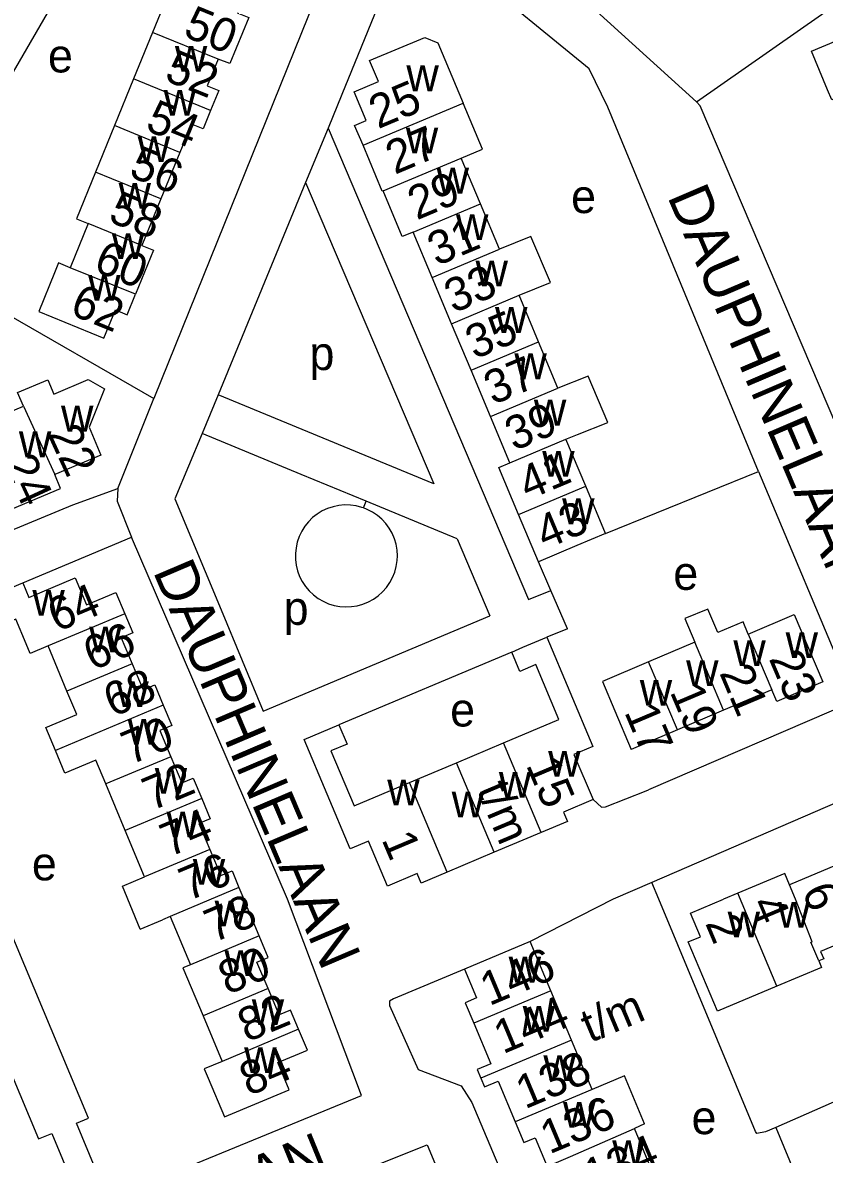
# Model space of a CAD drawing. Extents: x 157768 to 159790, y 387230 to 389604.
# Drawn here: x 158768.4 to 158864.1, y 388469.5 to 388604.7 of the extents above; entities that cross this region are included whole.
import ezdxf

# ---------------------------------------------------------------- set-up
doc = ezdxf.new("R2010")
doc.units = 0
for name, color, linetype in [('BLT_Basislijn', 7, 'Continuous'), ('BLT_Bebouwing', 7, 'Continuous'), ('BLT_Centroide', 7, 'Continuous'), ('BLT_Huisnummer', 7, 'Continuous'), ('BLT_Huisnummer_ tussenligend', 7, 'Continuous'), ('BLT_Huisnummer_reeks', 7, 'Continuous'), ('BLT_Onderverdeling_panden', 7, 'Continuous'), ('BLT_Straatnaam', 7, 'Continuous'), ('BLT_Vlakafsluiter', 7, 'Continuous')]:
    doc.layers.add(name, color=color, linetype=linetype)

msp = doc.modelspace()

# ---------------------------------------------------------------- linework, layer by layer
at = {"layer": 'BLT_Basislijn'}
for p, q in [((158848.78, 388595.18), (158874.98, 388613.54)), ((158804.81, 388592.04), (158802.14, 388585.55)), ((158804.81, 388592.04), (158828.75, 388535.77)), ((158802.14, 388585.55), (158791.68, 388560.24)), ((158802.14, 388585.55), (158817.43, 388549.6)), ((158752.5, 388577.95), (158784, 388559.78)), ((158779.72, 388549.02), (158784, 388559.78)), ((158791.68, 388560.24), (158789.77, 388555.62)), ((158817.43, 388549.6), (158791.68, 388560.24)), ((158801.62, 388550.72), (158789.77, 388555.62)), ((158809.37, 388547.52), (158801.62, 388550.72)), ((158837.95, 388543.66), (158856.2, 388551.05)), ((158820.22, 388543.04), (158809.37, 388547.52)), ((158768.37, 388537.78), (158781.37, 388543.21)), ((158820.22, 388543.04), (158824.14, 388533.83)), ((158831.39, 388536.88), (158829.92, 388540.29)), ((158828.75, 388535.77), (158831.39, 388536.88)), ((158833.38, 388532.3), (158831.39, 388536.88)), ((158792.05, 388534.54), (158797.07, 388522.45)), ((158797.07, 388522.45), (158824.14, 388533.83)), ((158833.38, 388532.3), (158830.93, 388531.28)), ((158826.75, 388529.52), (158806.1, 388520.84)), ((158875.29, 388515.8), (158843.47, 388502.02)), ((158858.27, 388472.75), (158871.67, 388440.58))]:
    msp.add_line(p, q, dxfattribs=at)
for points in [[(158752.5, 388577.95), (158756, 388582.29), (158766.39, 388597.28), (158772.92, 388608.56), (158776.78, 388616.43), (158781.2, 388626.96), (158792.74, 388668.52)], [(158848.78, 388595.18), (158820.24, 388621.14), (158817.54, 388623.31)], [(158809.51, 388621.86), (158808.32, 388620.05), (158784, 388559.78)], [(158856.2, 388551.05), (158838.2, 388594.58), (158835.97, 388599.15), (158821.48, 388611.04), (158818.68, 388612.35), (158817.09, 388612.4), (158813.77, 388611.42), (158811.86, 388609.35), (158806.47, 388596.08), (158804.81, 388592.04)], [(158877.6, 388529.55), (158876.7, 388530.29), (158849.23, 388594.74), (158848.78, 388595.18)], [(158789.77, 388555.62), (158786.54, 388547.79), (158792.05, 388534.54)], [(158856.2, 388551.05), (158867.29, 388524.65), (158867.48, 388523.59), (158843.07, 388513.05)], [(158743.37, 388533.93), (158743.54, 388534.06), (158743.9, 388534.46), (158774.34, 388547.09), (158779.72, 388549.02)], [(158779.72, 388549.02), (158779.65, 388547.53), (158781.37, 388543.21)], [(158809.05, 388546.72), (158808.85, 388546.79), (158808.18, 388546.97), (158807.49, 388547.06), (158806.79, 388547.08), (158806.09, 388547.02), (158805.41, 388546.87), (158804.75, 388546.65), (158804.12, 388546.36), (158803.52, 388545.99), (158802.97, 388545.56), (158802.48, 388545.07), (158802.04, 388544.53), (158801.67, 388543.94), (158801.37, 388543.31), (158801.14, 388542.65), (158800.99, 388541.97), (158800.92, 388541.28), (158800.92, 388540.58), (158801.01, 388539.89), (158801.18, 388539.21), (158801.42, 388538.55), (158801.74, 388537.93), (158802.12, 388537.35), (158802.57, 388536.82), (158803.08, 388536.34), (158803.63, 388535.92), (158804.24, 388535.57), (158804.88, 388535.29), (158805.54, 388535.08), (158806.23, 388534.96), (158806.92, 388534.91), (158807.62, 388534.94), (158808.31, 388535.05), (158808.98, 388535.24), (158809.63, 388535.5), (158810.24, 388535.84), (158810.81, 388536.24), (158811.32, 388536.71), (158811.79, 388537.24), (158812.18, 388537.81), (158812.52, 388538.42), (158812.77, 388539.07), (158812.96, 388539.74), (158813.06, 388540.43), (158813.09, 388540.99)], [(158813.09, 388540.99), (158813.05, 388541.69), (158812.93, 388542.38), (158812.73, 388543.05), (158812.46, 388543.69), (158812.11, 388544.3), (158811.7, 388544.86), (158811.23, 388545.37), (158810.7, 388545.83), (158810.12, 388546.22), (158809.5, 388546.54), (158809.05, 388546.72)], [(158778.58, 388464.15), (158808.82, 388476.57), (158799.98, 388500), (158781.37, 388543.21)], [(158778.58, 388464.15), (158774.78, 388473.27), (158776.21, 388473.86), (158755.39, 388523.57), (158753.12, 388522.63), (158749.99, 388530.03)], [(158748.73, 388529.24), (158751.69, 388522.02), (158749.43, 388521.09), (158770.23, 388471.39), (158771.83, 388472.05), (158775.66, 388462.85)], [(158836.45, 388511.9), (158837.47, 388511.01), (158837.94, 388511.04), (158842.81, 388512.94), (158843.07, 388513.05)], [(158843.47, 388502.02), (158838.86, 388500), (158828.95, 388494.95)], [(158858.27, 388472.75), (158857.02, 388472.22), (158855.99, 388472.03), (158855.83, 388472.28), (158844.29, 388500), (158843.47, 388502.02)], [(158925.92, 388502.32), (158920.27, 388500), (158858.27, 388472.75)], [(158821.11, 388491.65), (158812.62, 388488.1), (158812.14, 388487.84), (158812.15, 388487.34), (158815.59, 388479.7), (158820.7, 388477.74), (158821.99, 388475.76), (158841.52, 388429.43), (158841.92, 388428.6), (158843.29, 388428.39)], [(158743.87, 388438.13), (158745.5, 388438.98), (158746.04, 388441.22), (158804.21, 388465.72), (158816.65, 388470.68), (158826.54, 388446.97)]]:
    msp.add_lwpolyline(points, dxfattribs=at)
at = {"layer": 'BLT_Bebouwing'}
for p, q in [((158783.87, 388603.49), (158781.6, 388597.93)), ((158781.6, 388597.93), (158779.33, 388592.36)), ((158779.33, 388592.36), (158777.05, 388586.8)), ((158787.12, 388589.17), (158784.85, 388583.61)), ((158784.85, 388583.61), (158782.58, 388578.05)), ((158825.28, 388577.63), (158823.02, 388583.01)), ((158776.18, 388580.66), (158774.03, 388575.4)), ((158817.23, 388574.24), (158814.96, 388579.66)), ((158819.56, 388568.71), (158817.23, 388574.24)), ((158829.93, 388566.56), (158827.61, 388572.1)), ((158821.88, 388563.18), (158819.56, 388568.71)), ((158832.26, 388561.03), (158829.93, 388566.56)), ((158824.21, 388557.65), (158821.88, 388563.18)), ((158762.91, 388556.53), (158768.44, 388558.86)), ((158826.53, 388552.12), (158824.21, 388557.65)), ((158835.58, 388549.3), (158833.22, 388554.93)), ((158837.95, 388543.66), (158835.58, 388549.3)), ((158829.92, 388540.29), (158827.55, 388545.92)), ((158828.08, 388530.08), (158830.93, 388531.28)), ((158773.65, 388524.86), (158771.41, 388530.24)), ((158826.75, 388529.52), (158828.08, 388530.08)), ((158848.6, 388530.68), (158843.08, 388528.34)), ((158843.08, 388528.34), (158837.56, 388526)), ((158857.8, 388525.01), (158852.04, 388522.57)), ((158852.04, 388522.57), (158846.52, 388520.23)), ((158801.95, 388519.08), (158806.1, 388520.84)), ((158846.52, 388520.23), (158840.99, 388517.89)), ((158820.13, 388516.3), (158825.75, 388518.67)), ((158814.52, 388513.93), (158820.13, 388516.3)), ((158780.6, 388508.22), (158778.28, 388513.77)), ((158782.91, 388502.69), (158780.6, 388508.22)), ((158865.49, 388504.07), (158859.91, 388501.73)), ((158794.18, 388501.4), (158794.75, 388500)), ((158853.75, 388500.72), (158852.03, 388500)), ((158796.59, 388495.63), (158794.75, 388500)), ((158782.4, 388496.45), (158785.06, 388497.56)), ((158785.96, 388497.95), (158785.06, 388497.56)), ((158785.96, 388497.95), (158788.39, 388492.18)), ((158828.95, 388494.95), (158821.11, 388491.65)), ((158831.42, 388489.07), (158828.95, 388494.95)), ((158833.89, 388483.18), (158831.42, 388489.07)), ((158789.89, 388486.08), (158792.17, 388480.65)), ((158836.36, 388477.3), (158833.89, 388483.18)), ((158842.61, 388473.18), (158841.39, 388472.64))]:
    msp.add_line(p, q, dxfattribs=at)
for points in [[(158786.14, 388609.05), (158783.87, 388603.49)], [(158793.97, 388605.84), (158795.34, 388605.28), (158793.09, 388599.77), (158791.69, 388600.28)], [(158866.33, 388596.02), (158864.95, 388595.44), (158864.45, 388596.63), (158862.51, 388601.23), (158870.62, 388604.65), (158872.04, 388601.29), (158873.41, 388601.87), (158874.43, 388599.44)], [(158808.99, 388590.01), (158807.99, 388592.38), (158809.36, 388592.96), (158807.92, 388596.38), (158810.85, 388597.61), (158809.78, 388600.13), (158816.36, 388602.89), (158817.94, 388602.23), (158820.96, 388595.05)], [(158791.69, 388600.28), (158790.4, 388597.12), (158791.77, 388596.56), (158790.8, 388594.16)], [(158820.72, 388588.47), (158823.27, 388589.54), (158820.96, 388595.05)], [(158790.8, 388594.16), (158789.9, 388591.98), (158788.5, 388592.55), (158787.12, 388589.17)], [(158811.38, 388584.59), (158811.28, 388584.55), (158808.99, 388590.01)], [(158823.02, 388583.01), (158820.72, 388588.47)], [(158777.05, 388586.8), (158774.78, 388581.23), (158776.18, 388580.66)], [(158814.96, 388579.66), (158813.68, 388579.13), (158811.38, 388584.59)], [(158827.61, 388572.1), (158831.38, 388573.63), (158829.03, 388579.13), (158825.28, 388577.63)], [(158782.58, 388578.05), (158783.98, 388577.48), (158781.84, 388572.22)], [(158774.03, 388575.4), (158772.65, 388575.97), (158772.16, 388574.78), (158770.27, 388570.15), (158778.06, 388566.97), (158779.44, 388570.35), (158780.84, 388569.78), (158781.84, 388572.22)], [(158833.22, 388554.93), (158834.58, 388555.5), (158838.2, 388556.92), (158835.88, 388562.45), (158832.26, 388561.03)], [(158768.44, 388558.86), (158767.76, 388560.48), (158771.37, 388562), (158772.07, 388560.32), (158776.19, 388562.05), (158778.13, 388560.94), (158776.28, 388556.38), (158777.7, 388553.02), (158772.19, 388550.7)], [(158827.55, 388545.92), (158825.19, 388551.55), (158826.53, 388552.12)], [(158766.39, 388548.28), (158767.1, 388546.61), (158772.89, 388549.05), (158772.19, 388550.7)], [(158837.95, 388543.66), (158834.53, 388542.23), (158829.92, 388540.29)], [(158768.37, 388537.78), (158769.09, 388536.04), (158774.63, 388538.36)], [(158774.63, 388538.36), (158775.97, 388535.17), (158779.49, 388536.64), (158780.57, 388534.07)], [(158758.68, 388533.72), (158768.37, 388537.78)], [(158780.57, 388534.07), (158781.52, 388531.8), (158780.13, 388531.22), (158781.43, 388528.11)], [(158854.98, 388531.66), (158854.36, 388533.12), (158851.34, 388531.84), (158850.17, 388534.65), (158847.42, 388533.52), (158848.6, 388530.68)], [(158854.98, 388531.66), (158860.47, 388533.99), (158863.89, 388525.94), (158858.39, 388523.61), (158857.8, 388525.01)], [(158771.41, 388530.24), (158769.27, 388529.34), (158768.78, 388530.5), (158767.55, 388533.45), (158760.1, 388530.33), (158758.68, 388533.72)], [(158830.93, 388531.28), (158836.44, 388518.25), (158834.17, 388517.29), (158836.45, 388511.9)], [(158825.75, 388518.67), (158832.38, 388521.48), (158829.62, 388528.01), (158827.72, 388527.21), (158826.75, 388529.52)], [(158781.43, 388528.11), (158782.73, 388525.01), (158784.13, 388525.59), (158785.14, 388523.16)], [(158837.56, 388526), (158839.04, 388522.49), (158840.99, 388517.89)], [(158772.27, 388517.78), (158771.13, 388520.5), (158774.83, 388522.05), (158773.65, 388524.86)], [(158785.14, 388523.16), (158786.16, 388520.74), (158784.73, 388520.14), (158786.03, 388517.01)], [(158806.1, 388520.84), (158807.08, 388518.52), (158805.16, 388517.71), (158807.93, 388511.14), (158814.52, 388513.93)], [(158778.28, 388513.77), (158777.1, 388516.6), (158773.41, 388515.06), (158772.27, 388517.78)], [(158819.03, 388503.24), (158815.94, 388501.93), (158815.45, 388503.07), (158811.93, 388501.58), (158809.65, 388506.95), (158807.47, 388506.02), (158801.95, 388519.08)], [(158786.03, 388517.01), (158787.34, 388513.89), (158788.72, 388514.47), (158789.73, 388512.05)], [(158789.73, 388512.05), (158790.75, 388509.62), (158789.4, 388509.06), (158790.71, 388505.95)], [(158836.45, 388511.9), (158832.92, 388510.41), (158833.39, 388509.3), (158830.27, 388507.98)], [(158830.27, 388507.98), (158824.65, 388505.61)], [(158790.71, 388505.95), (158792.01, 388502.84), (158793.38, 388503.41), (158794.18, 388501.4)], [(158824.65, 388505.61), (158819.03, 388503.24)], [(158859.91, 388501.73), (158859.34, 388503.07), (158853.75, 388500.72)], [(158782.4, 388496.45), (158780.26, 388501.58), (158782.91, 388502.69)], [(158858.4, 388489.62), (158851.3, 388486.64), (158847.82, 388494.92), (158849.26, 388495.52), (158848.08, 388498.34), (158852.03, 388500)], [(158797.65, 388489.34), (158796.32, 388492.5), (158797.66, 388493.07), (158796.59, 388495.63)], [(158868.6, 388495.86), (158863.62, 388493.77), (158863.99, 388492.89), (158863.39, 388492.64)], [(158788.39, 388492.18), (158787.48, 388491.8), (158789.89, 388486.08)], [(158863.39, 388492.64), (158863.72, 388491.86), (158858.4, 388489.62)], [(158821.11, 388491.65), (158822.55, 388488.23), (158821.18, 388487.65), (158822.21, 388485.2)], [(158801.3, 388484.49), (158800.34, 388486.76), (158798.98, 388486.19), (158797.65, 388489.34)], [(158792.17, 388480.65), (158790.04, 388479.76), (158790.51, 388478.63), (158792.45, 388474.02), (158800.18, 388477.27), (158798.82, 388480.5), (158802.35, 388481.98), (158801.3, 388484.49)], [(158822.21, 388485.2), (158824.24, 388480.35), (158822.63, 388479.68), (158823.06, 388478.64)], [(158823.06, 388478.64), (158823.5, 388477.6), (158825.11, 388478.28), (158827.15, 388473.43)], [(158842.61, 388473.18), (158840.21, 388478.91), (158836.36, 388477.3)], [(158827.15, 388473.43), (158828.18, 388470.97), (158829.55, 388471.54), (158830.99, 388468.12), (158833.75, 388469.28)], [(158843.74, 388467.05), (158843.24, 388468.23), (158841.39, 388472.64)]]:
    msp.add_lwpolyline(points, dxfattribs=at)
at = {"layer": 'BLT_Onderverdeling_panden'}
for p, q in [((158791.69, 388600.28), (158783.87, 388603.49)), ((158790.8, 388594.16), (158781.6, 388597.93)), ((158808.99, 388590.01), (158820.96, 388595.05)), ((158787.12, 388589.17), (158779.33, 388592.36)), ((158784.85, 388583.61), (158777.05, 388586.8)), ((158814.96, 388579.66), (158823.02, 388583.01)), ((158782.58, 388578.05), (158776.18, 388580.66)), ((158817.23, 388574.24), (158825.28, 388577.63)), ((158781.84, 388572.22), (158774.03, 388575.4)), ((158819.56, 388568.71), (158827.61, 388572.1)), ((158821.88, 388563.18), (158829.93, 388566.56)), ((158824.21, 388557.65), (158832.26, 388561.03)), ((158768.44, 388558.86), (158772.19, 388550.7)), ((158826.53, 388552.12), (158833.22, 388554.93)), ((158827.55, 388545.92), (158835.58, 388549.3)), ((158780.57, 388534.07), (158771.41, 388530.24)), ((158854.98, 388531.66), (158857.8, 388525.01)), ((158852.04, 388522.57), (158848.6, 388530.68)), ((158781.43, 388528.11), (158773.65, 388524.86)), ((158846.52, 388520.23), (158843.08, 388528.34)), ((158785.14, 388523.16), (158772.27, 388517.78)), ((158830.27, 388507.98), (158825.75, 388518.67)), ((158786.03, 388517.01), (158778.28, 388513.77)), ((158824.65, 388505.61), (158820.13, 388516.3)), ((158819.03, 388503.24), (158814.52, 388513.93)), ((158789.73, 388512.05), (158780.6, 388508.22)), ((158790.71, 388505.95), (158782.91, 388502.69)), ((158794.18, 388501.4), (158785.96, 388497.95)), ((158858.4, 388489.62), (158853.75, 388500.72)), ((158796.59, 388495.63), (158788.39, 388492.18)), ((158797.65, 388489.34), (158789.89, 388486.08)), ((158831.42, 388489.07), (158822.21, 388485.2)), ((158801.3, 388484.49), (158792.17, 388480.65)), ((158833.89, 388483.18), (158823.06, 388478.64)), ((158836.36, 388477.3), (158827.15, 388473.43))]:
    msp.add_line(p, q, dxfattribs=at)
for points in [[(158811.38, 388584.59), (158820.72, 388588.47)], [(158863.39, 388492.64), (158862.45, 388494.87), (158862.6, 388494.93), (158860.63, 388500), (158859.91, 388501.73)], [(158833.75, 388469.28), (158841.39, 388472.64)]]:
    msp.add_lwpolyline(points, dxfattribs=at)
at = {"layer": 'BLT_Vlakafsluiter'}
msp.add_line((158809.05, 388546.72), (158809.37, 388547.52), dxfattribs=at)

# ---------------------------------------------------------------- texts
at = {"layer": 'BLT_Centroide'}
for s, p in [('e', (158771.38, 388598.71)), ('w', (158786.53, 388598.81)), ('w', (158814.17, 388596.47)), ('w', (158785.18, 388593.56)), ('w', (158814.1, 388589.06)), ('w', (158782.09, 388588)), ('w', (158817.77, 388584.25)), ('w', (158779.81, 388582.44)), ('e', (158833.83, 388581.92)), ('w', (158820.09, 388578.69)), ('w', (158779.01, 388576.44)), ('w', (158822.42, 388573.16)), ('w', (158776.17, 388571.47)), ('w', (158824.75, 388567.62)), ('p', (158802.6, 388563.18)), ('w', (158827.06, 388562.09)), ('w', (158772.94, 388555.84)), ('w', (158829.39, 388556.56)), ('w', (158767.91, 388552.78)), ('w', (158830.38, 388550.44)), ('w', (158832.76, 388544.78)), ('e', (158846.03, 388536.94)), ('w', (158769.52, 388533.84)), ('p', (158799.51, 388532.76)), ('w', (158776.3, 388529.47)), ('w', (158859.44, 388528.81)), ('w', (158853.2, 388527.84)), ('w', (158847.56, 388525.45)), ('w', (158779.54, 388522.94)), ('w', (158842.03, 388523.12)), ('e', (158819.39, 388520.63)), ('w', (158780.88, 388518.47)), ('w', (158831.09, 388514.64)), ('w', (158784.13, 388512.62)), ('w', (158825.2, 388512.14)), ('w', (158811.88, 388511.22)), ('w', (158819.58, 388509.77)), ('w', (158785.53, 388507.38)), ('e', (158769.46, 388502.26)), ('w', (158788.67, 388501.75)), ('w', (158791.27, 388496.78)), ('w', (158858.48, 388496.62)), ('w', (158852.52, 388495.45)), ('w', (158792.45, 388490.84)), ('w', (158826.38, 388490.06)), ('w', (158795.71, 388485)), ('w', (158828.05, 388484.19)), ('w', (158794.8, 388479.25)), ('w', (158830.52, 388478.31)), ('w', (158832.87, 388472.72)), ('e', (158848.21, 388471.96)), ('w', (158838.74, 388468.16))]:
    msp.add_text(s, height=4, dxfattribs=at).set_placement(p)
at = {"layer": 'BLT_Huisnummer'}
for s, rotation, p in [('50', 337.7261, (158787.37, 388603.1)), ('25', 22.803, (158810.78, 388591.92)), ('54', 337.7261, (158782.85, 388591.88)), ('29', 22.803, (158815.41, 388581.04)), ('58', 337.7261, (158778.42, 388580.99)), ('33', 22.8021, (158819.78, 388569.93)), ('62', 337.7261, (158773.84, 388569.89)), ('37', 22.7986, (158824.51, 388558.98)), ('22', 294.6958, (158771.28, 388555.57)), ('43', 22.7909, (158830.7, 388541.73)), ('64', 22.7113, (158772.43, 388531.86)), ('23', 292.9748, (158857.4, 388528.74)), ('68', 22.7113, (158779.11, 388521.7)), ('17', 292.9654, (158840.14, 388522.37)), ('72', 22.7113, (158783.74, 388510.52)), ('76', 22.7113, (158788.12, 388499.75)), ('6', 292.8103, (158861.34, 388500.99)), ('2', 292.8103, (158849.8, 388497.16)), ('80', 22.7113, (158792.8, 388488.56)), ('146', 22.7679, (158824.06, 388487.23)), ('84', 22.7113, (158795.33, 388476.47)), ('136', 22.7679, (158831.24, 388469.53)), ('134', 22.7679, (158836.38, 388464.92))]:
    msp.add_text(s, height=4, rotation=rotation, dxfattribs=at).set_placement(p)
at = {"layer": 'BLT_Huisnummer_ tussenligend'}
for s, rotation, p in [('52', 337.8006, (158785.13, 388597.83)), ('27', 22.803, (158812.78, 388586.48)), ('56', 337.8006, (158780.89, 388586.36)), ('31', 22.8021, (158817.78, 388575.55)), ('60', 337.8006, (158776.66, 388575.08)), ('35', 22.7986, (158822.31, 388564.42)), ('39', 22.798, (158827.02, 388553.48)), ('24', 294.6958, (158765.95, 388552.03)), ('41', 22.798, (158828.65, 388547.61)), ('66', 22.7113, (158776.69, 388527.25)), ('21', 292.9654, (158851.49, 388527.04)), ('19', 292.9654, (158845.58, 388524.78)), ('70', 22.7113, (158781.23, 388516.02)), ('74', 22.7113, (158785.86, 388505.01)), ('78', 22.7113, (158791.14, 388494.78)), ('4', 292.8103, (158855.21, 388499.48)), ('82', 22.7113, (158795.12, 388482.89))]:
    msp.add_text(s, height=4, rotation=rotation, dxfattribs=at).set_placement(p)
at = {"layer": 'BLT_Huisnummer_reeks'}
for s, rotation, p in [('15', 292.9144, (158828.41, 388516.05)), ('t/m', 292.9185, (158822.54, 388513.09)), ('1', 292.9185, (158811.17, 388507.15)), ('144', 22.7655, (158825.69, 388481.49)), ('t/m', 22.7847, (158836.09, 388482.83)), ('138', 22.7655, (158828.32, 388474.91))]:
    msp.add_text(s, height=4, rotation=rotation, dxfattribs=at).set_placement(p)
at = {"layer": 'BLT_Straatnaam'}
for s, rotation, p in [('DAUPHINELAAN', 293.1356, (158845.27, 388583.92)), ('DAUPHINELAAN', 293.0471, (158783.87, 388539.16)), ('LORRAINELAAN', 22.2595, (158757.4, 388448.1))]:
    msp.add_text(s, height=4.9999, rotation=rotation, dxfattribs=at).set_placement(p)

doc.saveas('drawing.dxf')
